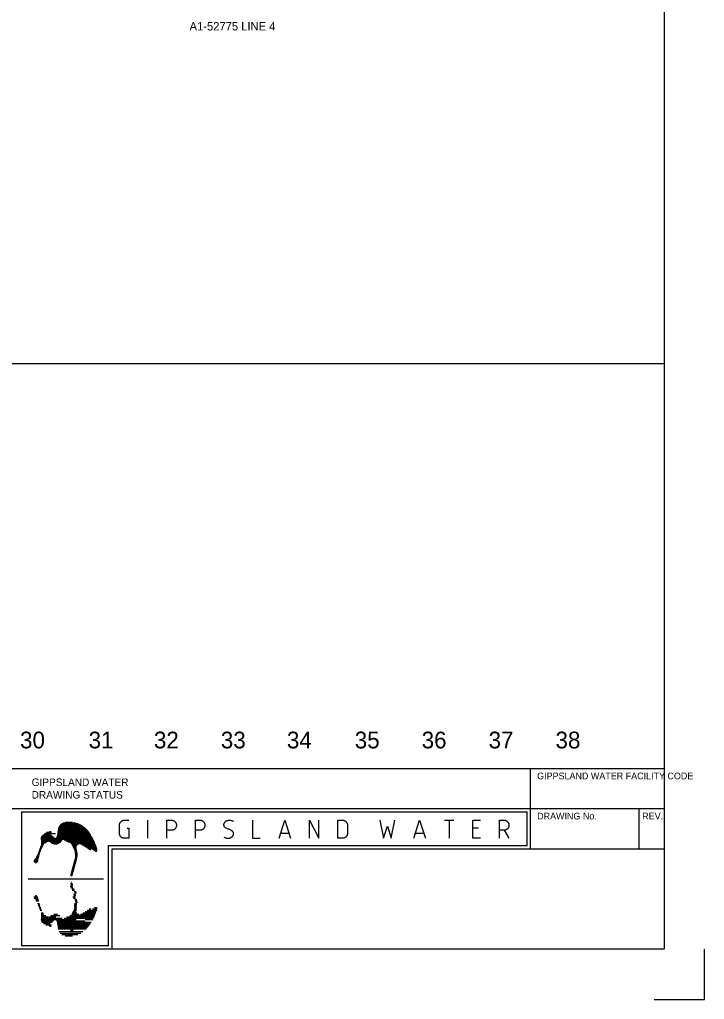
# Model space of a CAD drawing. Extents: x 0 to 841, y 0 to 594.
# Drawn here: x 636.4 to 841, y 0 to 292.8 of the extents above; entities that cross this region are included whole.
import ezdxf

# ---------------------------------------------------------------- set-up
doc = ezdxf.new("R2010")
doc.units = 0
doc.layers.add('A1BORDER', color=7, linetype='Continuous')
doc.layers.add('Level 1', color=7, linetype='Continuous')

msp = doc.modelspace()

# ---------------------------------------------------------------- linework, layer by layer
at = {"layer": 'A1BORDER'}
for p, q in [((829, 581), (829, 15)), ((592.5, 69), (829, 69)), ((789, 45), (789, 69)), ((28, 57), (829, 57)), ((637, 56), (788, 56)), ((637, 56), (637, 16)), ((788, 46), (788, 56)), ((821.5, 45), (821.5, 57)), ((649.39, 52.72), (653.15, 52.72)), ((650.01, 52.92), (652.2, 52.92)), ((644.54, 49.92), (645.36, 49.92)), ((645.37, 50.12), (645.86, 50.12)), ((647.75, 49.92), (657.17, 49.92)), ((647.78, 50.12), (657.02, 50.12)), ((647.81, 50.32), (656.86, 50.32)), ((647.85, 50.52), (656.69, 50.52)), ((647.88, 50.72), (656.5, 50.72)), ((647.91, 50.92), (656.3, 50.92)), ((647.96, 51.12), (656.08, 51.12)), ((648.03, 51.32), (655.85, 51.32)), ((648.12, 51.52), (655.59, 51.52)), ((648.23, 51.72), (655.31, 51.72)), ((648.37, 51.92), (655, 51.92)), ((648.53, 52.12), (654.64, 52.12)), ((648.74, 52.32), (654.24, 52.32)), ((649.02, 52.52), (653.76, 52.52)), ((642.73, 48.12), (658.25, 48.12)), ((642.74, 47.92), (658.35, 47.92)), ((642.75, 48.32), (646.79, 48.32)), ((642.79, 47.72), (649.08, 47.72)), ((642.81, 48.52), (646.55, 48.52)), ((642.83, 47.52), (648.95, 47.52)), ((642.85, 47.31), (644.88, 47.31)), ((642.87, 47.12), (644.57, 47.12)), ((642.88, 46.92), (644.23, 46.92)), ((642.9, 48.72), (646.37, 48.72)), ((643.04, 48.92), (646.16, 48.92)), ((643.26, 49.12), (645.9, 49.12)), ((643.54, 49.32), (645.57, 49.32)), ((643.85, 49.52), (647.09, 49.52)), ((644.18, 49.72), (645.89, 49.72)), ((645.14, 47.31), (648.83, 47.31)), ((645.49, 47.12), (648.67, 47.12)), ((645.76, 46.92), (648.42, 46.92)), ((647.19, 48.32), (658.14, 48.32)), ((647.42, 48.52), (658.03, 48.52)), ((647.54, 48.72), (657.92, 48.72)), ((647.61, 48.92), (657.8, 48.92)), ((647.63, 49.12), (657.68, 49.12)), ((647.66, 49.32), (657.57, 49.32)), ((647.69, 49.52), (657.44, 49.52)), ((647.71, 49.72), (657.31, 49.72)), ((649.72, 47.72), (658.45, 47.72)), ((650.12, 47.52), (658.55, 47.52)), ((650.48, 47.31), (658.64, 47.31)), ((650.87, 47.12), (658.73, 47.12)), ((651.36, 46.92), (658.82, 46.92)), ((641.99, 43.92), (642.48, 43.92)), ((642.06, 44.12), (642.55, 44.12)), ((642.13, 44.32), (642.62, 44.32)), ((642.21, 44.52), (642.69, 44.52)), ((642.28, 44.72), (642.76, 44.72)), ((642.35, 44.92), (642.83, 44.92)), ((642.43, 45.12), (642.9, 45.12)), ((642.5, 45.32), (643, 45.32)), ((642.57, 45.52), (643.1, 45.52)), ((642.65, 45.72), (643.2, 45.72)), ((642.72, 45.92), (643.3, 45.92)), ((642.79, 46.12), (643.4, 46.12)), ((642.84, 46.32), (643.5, 46.32)), ((642.87, 46.52), (643.6, 46.52)), ((642.88, 46.72), (643.83, 46.72)), ((646.05, 46.72), (648.11, 46.72)), ((646.62, 46.52), (647.67, 46.52)), ((651.76, 46.72), (658.9, 46.72)), ((651.88, 46.52), (654.15, 46.52)), ((651.99, 46.32), (653.71, 46.32)), ((652.1, 46.12), (653.52, 46.12)), ((652.2, 45.92), (653.4, 45.92)), ((652.31, 45.72), (653.33, 45.72)), ((652.41, 45.52), (653.31, 45.52)), ((652.5, 45.32), (653.34, 45.32)), ((652.6, 45.12), (653.38, 45.12)), ((652.69, 44.92), (653.41, 44.92)), ((652.78, 44.72), (653.44, 44.72)), ((652.83, 44.52), (653.48, 44.52)), ((652.86, 44.32), (653.53, 44.32)), ((652.89, 44.12), (653.57, 44.12)), ((652.91, 43.92), (653.62, 43.92)), ((654.57, 46.52), (658.99, 46.52)), ((655, 46.32), (659.07, 46.32)), ((655.31, 46.12), (659.14, 46.12)), ((655.62, 45.92), (659.22, 45.92)), ((655.93, 45.72), (659.29, 45.72)), ((656.24, 45.52), (659.35, 45.52)), ((656.55, 45.32), (659.42, 45.32)), ((656.86, 45.12), (657.74, 45.12)), ((657.17, 44.92), (657.68, 44.92)), ((657.51, 44.72), (657.54, 44.72)), ((657.91, 45.12), (659.48, 45.12)), ((658.19, 44.92), (659.54, 44.92)), ((658.47, 44.72), (659.59, 44.72)), ((658.75, 44.52), (659.58, 44.52)), ((659.02, 44.32), (659.47, 44.32)), ((663, 46), (788, 46)), ((663, 16), (663, 46)), ((664, 45), (829, 45)), ((664, 15), (664, 45)), ((640.62, 41.32), (641.88, 41.32)), ((640.63, 41.52), (641.93, 41.52)), ((640.72, 41.12), (641.73, 41.12)), ((640.73, 41.72), (641.95, 41.72)), ((640.9, 41.92), (641.97, 41.92)), ((641.1, 42.12), (642, 42.12)), ((641.25, 42.31), (642.04, 42.31)), ((641.37, 42.52), (642.09, 42.52)), ((641.46, 42.72), (642.15, 42.72)), ((641.55, 42.92), (642.2, 42.92)), ((641.64, 43.12), (642.25, 43.12)), ((641.73, 43.32), (642.3, 43.32)), ((641.82, 43.51), (642.35, 43.51)), ((641.91, 43.72), (642.41, 43.72)), ((652.63, 41.12), (653.26, 41.12)), ((652.68, 41.32), (653.31, 41.32)), ((652.74, 41.52), (653.37, 41.52)), ((652.79, 41.72), (653.41, 41.72)), ((652.85, 41.92), (653.45, 41.92)), ((652.9, 42.12), (653.49, 42.12)), ((652.94, 43.72), (653.67, 43.72)), ((652.95, 42.31), (653.53, 42.31)), ((652.97, 43.51), (653.71, 43.51)), ((652.99, 42.52), (653.57, 42.52)), ((653, 43.32), (653.69, 43.32)), ((653.02, 43.12), (653.67, 43.12)), ((653.03, 42.72), (653.61, 42.72)), ((653.05, 42.92), (653.64, 42.92)), ((641.03, 40.92), (641.43, 40.92)), ((651.82, 38.12), (652.44, 38.12)), ((651.87, 38.32), (652.5, 38.32)), ((651.92, 38.52), (652.55, 38.52)), ((651.98, 38.72), (652.61, 38.72)), ((652.03, 38.92), (652.66, 38.92)), ((652.09, 39.12), (652.72, 39.12)), ((652.14, 39.32), (652.77, 39.32)), ((652.2, 39.52), (652.82, 39.52)), ((652.25, 39.72), (652.88, 39.72)), ((652.3, 39.92), (652.93, 39.92)), ((652.36, 40.12), (652.99, 40.12)), ((652.41, 40.32), (653.04, 40.32)), ((652.47, 40.52), (653.1, 40.52)), ((652.52, 40.72), (653.15, 40.72)), ((652.57, 40.92), (653.2, 40.92)), ((638.93, 35.98), (661.47, 35.98)), ((651.63, 37.32), (652.23, 37.32)), ((651.64, 37.12), (652.17, 37.12)), ((651.65, 37.52), (652.28, 37.52)), ((651.71, 37.72), (652.34, 37.72)), ((651.76, 37.92), (652.39, 37.92)), ((651.79, 36.92), (651.9, 36.92)), ((651.54, 33.84), (652.17, 33.84)), ((651.63, 34.64), (652.23, 34.64)), ((651.65, 33.44), (652.28, 33.44)), ((651.71, 34.24), (652.34, 34.24)), ((651.79, 35.04), (651.9, 35.04)), ((652.03, 33.04), (652.66, 33.04)), ((652.14, 32.64), (652.77, 32.64)), ((652.66, 32.24), (653.29, 32.24)), ((640.62, 30.64), (641.88, 30.64)), ((640.73, 30.24), (641.95, 30.24)), ((641.03, 31.04), (641.43, 31.04)), ((641.1, 29.84), (642, 29.84)), ((641.37, 29.44), (642.09, 29.44)), ((652.34, 30.64), (652.97, 30.64)), ((652.45, 30.24), (653.07, 30.24)), ((652.47, 31.44), (653.1, 31.44)), ((652.57, 31.04), (653.2, 31.04)), ((652.77, 31.84), (653.4, 31.84)), ((652.9, 29.84), (653.49, 29.84)), ((652.99, 29.44), (653.57, 29.44)), ((641.73, 28.64), (642.3, 28.64)), ((641.91, 28.24), (642.41, 28.24)), ((642.06, 27.84), (642.55, 27.84)), ((642.21, 27.44), (642.69, 27.44)), ((642.35, 27.04), (642.83, 27.04)), ((642.5, 26.64), (643, 26.64)), ((652.5, 26.64), (653.34, 26.64)), ((652.66, 27.84), (653.35, 27.84)), ((652.69, 27.04), (653.41, 27.04)), ((652.72, 28.24), (653.44, 28.24)), ((652.77, 28.64), (653.46, 28.64)), ((652.83, 27.44), (653.48, 27.44)), ((653.05, 29.04), (653.64, 29.04)), ((656.55, 26.64), (659.42, 26.64)), ((657.17, 27.04), (657.68, 27.04)), ((658.19, 27.04), (659.54, 27.04)), ((658.75, 27.44), (659.58, 27.44)), ((642.73, 23.84), (653.27, 23.84)), ((642.79, 25.84), (643.4, 25.84)), ((642.79, 24.24), (649.08, 24.24)), ((642.81, 23.44), (646.55, 23.44)), ((642.85, 24.65), (644.88, 24.65)), ((642.87, 25.44), (643.6, 25.44)), ((642.88, 25.04), (644.23, 25.04)), ((645.14, 24.65), (647.18, 24.65)), ((645.76, 25.04), (648.42, 25.04)), ((646.62, 25.44), (647.67, 25.44)), ((647.42, 23.44), (655.89, 23.44)), ((649.72, 24.24), (658.45, 24.24)), ((650.48, 24.65), (658.64, 24.65)), ((651.36, 25.04), (658.82, 25.04)), ((651.88, 25.44), (654.15, 25.44)), ((652.1, 25.84), (653.52, 25.84)), ((652.31, 26.24), (653.33, 26.24)), ((654.57, 25.44), (658.99, 25.44)), ((655.31, 25.84), (659.14, 25.84)), ((655.93, 26.24), (659.29, 26.24)), ((655.94, 23.84), (658.25, 23.84)), ((643.04, 23.04), (646.16, 23.04)), ((643.54, 22.64), (645.57, 22.64)), ((644.18, 22.24), (645.89, 22.24)), ((645.37, 21.84), (645.86, 21.84)), ((647.61, 23.04), (657.8, 23.04)), ((647.66, 22.64), (657.57, 22.64)), ((647.71, 22.24), (657.31, 22.24)), ((647.78, 21.84), (657.02, 21.84)), ((647.85, 21.44), (656.69, 21.44)), ((647.91, 21.04), (656.3, 21.04)), ((651.57, 20.64), (652.44, 20.64)), ((648.23, 20.24), (655.31, 20.24)), ((648.53, 19.84), (654.64, 19.84)), ((649.02, 19.44), (653.76, 19.44)), ((650.01, 19.04), (652.2, 19.04)), ((829, 15), (28, 15)), ((663, 16), (637, 16)), ((829, 15), (829, 15)), ((841, 0), (841, 15)), ((826, 0), (841, 0))]:
    msp.add_line(p, q, dxfattribs=at)
for points in [[(668.49, 51.15), (669.06, 51.15), (669.06, 48.16), (667.64, 48.16), (667.51, 48.16), (667.39, 48.18), (667.28, 48.21), (667.15, 48.25), (667.04, 48.3), (666.93, 48.36), (666.82, 48.43), (666.73, 48.51), (666.64, 48.6), (666.55, 48.7), (666.48, 48.8), (666.41, 48.91), (666.35, 49.02), (666.31, 49.14), (666.27, 49.27), (666.24, 49.39), (666.22, 49.52), (666.22, 49.66), (666.22, 52.05), (666.22, 52.18), (666.24, 52.31), (666.27, 52.43), (666.31, 52.56), (666.35, 52.67), (666.41, 52.79), (666.48, 52.9), (666.55, 53), (666.64, 53.1), (666.73, 53.19), (666.82, 53.27), (666.93, 53.34), (667.04, 53.4), (667.15, 53.45), (667.28, 53.49), (667.39, 53.52), (667.51, 53.54), (667.64, 53.54), (669.06, 53.54)], [(674.74, 48.16), (674.74, 53.54)], [(680.42, 48.16), (680.42, 53.54), (681.84, 53.54), (681.96, 53.54), (682.08, 53.52), (682.2, 53.49), (682.32, 53.45), (682.43, 53.4), (682.54, 53.34), (682.65, 53.27), (682.74, 53.19), (682.84, 53.1), (682.92, 53), (682.99, 52.9), (683.06, 52.79), (683.12, 52.67), (683.17, 52.56), (683.21, 52.43), (683.23, 52.31), (683.25, 52.18), (683.26, 52.05), (683.25, 51.91), (683.23, 51.78), (683.21, 51.66), (683.17, 51.53), (683.12, 51.42), (683.06, 51.3), (682.99, 51.19), (682.92, 51.09), (682.84, 50.99), (682.74, 50.9), (682.65, 50.82), (682.54, 50.75), (682.43, 50.69), (682.32, 50.64), (682.2, 50.6), (682.08, 50.57), (681.96, 50.55), (681.84, 50.55), (680.42, 50.55)], [(688.93, 48.16), (688.93, 53.54), (690.35, 53.54), (690.47, 53.54), (690.59, 53.52), (690.71, 53.49), (690.83, 53.45), (690.94, 53.4), (691.05, 53.34), (691.16, 53.27), (691.26, 53.19), (691.35, 53.1), (691.43, 53), (691.51, 52.9), (691.57, 52.79), (691.63, 52.67), (691.68, 52.56), (691.72, 52.43), (691.75, 52.31), (691.76, 52.18), (691.77, 52.05), (691.76, 51.91), (691.75, 51.78), (691.72, 51.66), (691.68, 51.53), (691.63, 51.42), (691.57, 51.3), (691.51, 51.19), (691.43, 51.09), (691.35, 50.99), (691.26, 50.9), (691.16, 50.82), (691.05, 50.75), (690.94, 50.69), (690.83, 50.64), (690.71, 50.6), (690.59, 50.57), (690.47, 50.55), (690.35, 50.55), (688.93, 50.55)], [(697.45, 48.46), (697.67, 48.36), (697.9, 48.27), (698.12, 48.21), (698.36, 48.17), (698.6, 48.16), (698.84, 48.16), (698.87, 48.16), (699.03, 48.18), (699.18, 48.21), (699.33, 48.26), (699.48, 48.32), (699.62, 48.4), (699.72, 48.46), (699.81, 48.53), (699.9, 48.61), (699.98, 48.69), (700.05, 48.78), (700.11, 48.88), (700.17, 48.99), (700.22, 49.09), (700.25, 49.21), (700.28, 49.32), (700.29, 49.36), (700.3, 49.44), (700.3, 49.52), (700.3, 49.61), (700.29, 49.69), (700.27, 49.77), (700.25, 49.86), (700.22, 49.93), (700.18, 50.01), (700.14, 50.09), (700.09, 50.15), (700.04, 50.21), (700.01, 50.25), (699.85, 50.39), (699.69, 50.51), (699.52, 50.61), (699.34, 50.7), (699.15, 50.78), (698.95, 50.83), (698.87, 50.85), (698.68, 50.9), (698.49, 50.96), (698.3, 51.04), (698.12, 51.14), (697.96, 51.26), (697.8, 51.39), (697.73, 51.45), (697.67, 51.51), (697.62, 51.57), (697.58, 51.64), (697.53, 51.71), (697.5, 51.79), (697.47, 51.87), (697.46, 51.95), (697.44, 52.04), (697.43, 52.12), (697.43, 52.21), (697.44, 52.29), (697.45, 52.35), (697.47, 52.46), (697.51, 52.58), (697.55, 52.69), (697.61, 52.79), (697.67, 52.89), (697.74, 52.99), (697.82, 53.07), (697.9, 53.15), (697.99, 53.23), (698.02, 53.24), (698.15, 53.33), (698.3, 53.4), (698.44, 53.45), (698.6, 53.5), (698.75, 53.52), (698.87, 53.54), (699.11, 53.55), (699.35, 53.53), (699.58, 53.49), (699.82, 53.43), (700.04, 53.35), (700.27, 53.25)], [(705.96, 53.54), (705.96, 48.16), (708.23, 48.16)], [(713.91, 48.16), (715.61, 53.54), (717.32, 48.16)], [(722.99, 48.16), (722.99, 53.54), (725.83, 48.16), (725.83, 53.54)], [(731.52, 48.16), (731.52, 53.54), (732.94, 53.54), (733.06, 53.54), (733.18, 53.52), (733.3, 53.49), (733.42, 53.45), (733.53, 53.4), (733.64, 53.34), (733.75, 53.27), (733.84, 53.19), (733.94, 53.1), (734.02, 53), (734.09, 52.9), (734.16, 52.79), (734.22, 52.67), (734.27, 52.56), (734.31, 52.43), (734.33, 52.31), (734.35, 52.18), (734.36, 52.05), (734.36, 49.66), (734.35, 49.52), (734.33, 49.39), (734.31, 49.27), (734.27, 49.14), (734.22, 49.02), (734.16, 48.91), (734.09, 48.8), (734.02, 48.7), (733.94, 48.6), (733.84, 48.51), (733.75, 48.43), (733.64, 48.36), (733.53, 48.3), (733.42, 48.25), (733.3, 48.21), (733.18, 48.18), (733.06, 48.16), (732.94, 48.16), (731.52, 48.16)], [(744.01, 53.54), (745.14, 48.16), (746.28, 51.75), (747.41, 48.16), (748.55, 53.54)], [(754.22, 48.16), (755.92, 53.54), (757.63, 48.16)], [(763.31, 53.54), (766.15, 53.54)], [(764.73, 53.54), (764.73, 48.16)], [(774.09, 48.16), (771.82, 48.16), (771.82, 53.54), (774.09, 53.54)], [(779.78, 48.16), (779.78, 53.54), (781.2, 53.54), (781.32, 53.54), (781.44, 53.52), (781.56, 53.49), (781.68, 53.45), (781.79, 53.4), (781.9, 53.34), (782.01, 53.27), (782.1, 53.19), (782.2, 53.1), (782.28, 53), (782.35, 52.9), (782.42, 52.79), (782.48, 52.67), (782.53, 52.56), (782.56, 52.43), (782.59, 52.31), (782.61, 52.18), (782.61, 52.05), (782.61, 51.91), (782.59, 51.78), (782.56, 51.66), (782.53, 51.53), (782.48, 51.42), (782.42, 51.3), (782.35, 51.19), (782.28, 51.09), (782.2, 50.99), (782.1, 50.9), (782.01, 50.82), (781.9, 50.75), (781.79, 50.69), (781.68, 50.64), (781.56, 50.6), (781.44, 50.57), (781.32, 50.55), (781.2, 50.55), (779.78, 50.55)], [(773.53, 51.15), (771.82, 51.15)], [(781.2, 50.55), (782.61, 48.16)], [(714.48, 49.66), (716.75, 49.66)], [(754.79, 49.66), (757.06, 49.66)]]:
    msp.add_lwpolyline(points, dxfattribs=at)
at = {"layer": 'Level 1'}
msp.add_line((28, 190), (829, 190), dxfattribs=at)

# ---------------------------------------------------------------- texts
at = {"layer": 'A1BORDER'}
for s, height, p in [('GIPPSLAND WATER FACILITY CODE', 1.99998, (791.03, 65.77)), ('GIPPSLAND WATER', 2.25, (640, 63.75)), ('DRAWING STATUS', 2.25, (640, 60)), ('DRAWING No.', 1.99998, (791.03, 53.77)), ('REV.', 1.99998, (822.43, 53.77))]:
    msp.add_text(s, height=height, dxfattribs=at).set_placement(p)
at = {"layer": 'Level 1'}
for s, height, p in [('A1-52775 LINE 4', 2.50002, (687.17519, 289.49997)), ('30', 4.99998, (636.52, 75)), ('31', 4.99998, (657.01, 75)), ('32', 4.99998, (676.52, 75)), ('33', 4.99998, (696.52, 75)), ('34', 4.99998, (716.26, 75)), ('35', 4.99998, (736.52, 75)), ('36', 4.99998, (756.52, 75)), ('37', 4.99998, (776.52, 75)), ('38', 4.99998, (796.52, 75))]:
    msp.add_text(s, height=height, dxfattribs=at).set_placement(p)

doc.saveas('drawing.dxf')
